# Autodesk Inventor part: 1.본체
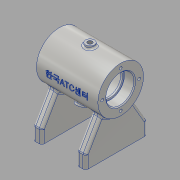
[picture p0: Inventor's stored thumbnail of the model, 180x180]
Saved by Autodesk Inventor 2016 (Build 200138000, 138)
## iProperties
Created: 2018-05
Part Number: 1.본체
Material: 알루미늄 6061
Document SubType Name: Modeling
Designer: 605-15
Density: 2.7 g/cm^3
Appearance: 알루미늄 - 평지
Mass: 317.681 g
Surface Area: 375.844 cm^2
Volume: 117.66 cm^3
Author: 605-15
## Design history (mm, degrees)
sketch "스케치1"
  geometry: L1 (-35, 0)-(35, 0); L2 (-35, 16)-(-35, 26); L3 (-35, 26)-(35, 26); L4 (35, 26)-(35, 16); L5 (35, 16)-(23, 16); L6 (23, 16)-(23, 14); L7 (23, 14)-(21, 14); L8 (21, 14)-(21, 21); L9 (21, 21)-(-21, 21); L10 (-21, 21)-(-21, 14); L11 (-21, 14)-(-23, 14); L12 (-23, 14)-(-23, 16); L13 (-23, 16)-(-35, 16); 1 further point
  constraints: 26 end point, 10 perpendicular, 3 point on line, 2 collinear, 2 vertical alignment, 1 horizontal, 1 midpoint, 1 vertical
  dimensions: "d0" = 70 distance of L1.start L1.end; "d1" = 35 distance of point (0, 0) L1.start; "d2" = 52 diameter of L3 L1; "d3" = 32 diameter of L5 L1; "d4" = 42 diameter of L9 L1; "d5" = 28 diameter of L7 L1; "d6" = 12 distance of L4.end L5.end; "d7" = 42 distance of L8.end L9.end
revolve "회전1" sketch "스케치1" stored, may be unused: angle "d8" = 90 deg
sketch "스케치2"
  geometry: L1 (-19.386, -17.325)-(-50, -35); L2 (-50, -35)-(-65, -35); L3 (-65, -35)-(-65, 35); L4 (-65, 35)-(-50, 35); L5 (-50, 35)-(-19.386, 17.325); A1 r 26 centre (0, 0) between (-19.386, -17.325) and (-19.386, 17.325) reference; 2 further points
  constraints: 10 end point, 2 perpendicular, 2 point on circle, 1 equal length, 1 horizontal, 1 horizontal alignment, 1 midpoint
  dimensions: "d9" = 30 deg angle of L4 L5; "d10" = 15 distance of L3.end L4.end; "d11" = 65 distance from line of point (0, 0) L3; "d12" = 70 distance between parallel lines of L2 L4; "d13" = 30 deg angle of L2 L1 (= d9)
extrude "돌출1" join sketch "스케치2" stored distance "d14" = 60; taper "d15" = 0 deg
sketch "스케치3"
  geometry: L1 (-19.386, 17.325)-(-50, 35) reference; L2 (-50, 35)-(-65, 35) reference; L3 (-65, 35)-(-65, -35) reference; L4 (-65, -35)-(-50, -35) reference; L5 (-50, -35)-(-19.386, -17.325) reference; A1 r 26 centre (0, 0) between (-19.386, 17.325) and (-19.386, -17.325) reference; 1 further point
extrude "돌출2" cut sketch "스케치3" stored distance "d16" = 40; taper "d17" = 0 deg
sketch "스케치4" dims "d18" = 42
  geometry: 3 further points
  constraints: 2 vertical alignment, 1 coincident, 2 other
hole "구멍1" sketch "스케치4" at (0, 21) diameter "d19" = 3.242; stored, may be unused: countersink angle "d23" = 90 deg, drill point angle "d25" = 118 deg; dims "d20" = 8, "d21" = 4, "d22" = 2, "d24" = 10
node "작업 평면1"
sketch "스케치5"
  geometry: C1 r 5 at (0, 0); 1 further point
  constraints: 1 centre point, 1 coincident
  dimensions: "d30" = 10 diameter of C1
extrude "돌출3" join sketch "스케치5" stored distance "d31" = 40; taper "d32" = 0 deg
sketch "스케치6"
  geometry: 1 further point
hole "구멍2" sketch "스케치6" at (0, 0) diameter "d33" = 5.188; stored, may be unused: countersink angle "d37" = 90 deg, drill point angle "d39" = 118 deg; dims "d34" = 16, "d35" = 4, "d36" = 2, "d38" = 16
sketch "스케치7"
  geometry: L1 (0, 0)-(-27.251, 9.919); L2 (0, 0)-(29, 0)
  constraints: 4 end point, 1 equal length, 1 horizontal
  dimensions: "d40" = 29 distance of L1.start L1.end; "d41" = 160 deg angle of L2 L1
node "작업 평면2"
sketch "스케치8"
  geometry: C1 r 6 at (0, 0); 1 further point
  constraints: 1 centre point, 1 coincident
  dimensions: "d42" = 12 diameter of C1
extrude "돌출4" join sketch "스케치8" stored distance "d43" = 40; taper "d44" = 0 deg
hole "구멍3" diameter "d47" = 5.188; stored, may be unused: countersink angle "d51" = 90 deg, drill point angle "d53" = 118 deg; dims "d45" = 10, "d46" = 10, "d48" = 16, "d49" = 4, "d50" = 2, "d52" = 16
sketch "스케치9"
  geometry: 5 further points
  constraints: 2 horizontal alignment, 2 vertical alignment
  dimensions: "d54" = 20 vertical distance of point (-30, 35) point (-5, 15); "d55" = 50 distance of point (-55, 15) point (-5, 15); "d56" = 25 horizontal distance of point (-30, 35) point (-5, 15); "d57" = 20 vertical distance of point (-5, 55) point (-30, 35)
hole "구멍4" sketch "스케치9" at (-5, 55), (-5, 15), (-55, 55), (-55, 15) diameter "d58" = 4.134; stored, may be unused: countersink angle "d62" = 90 deg, drill point angle "d64" = 118 deg; dims "d59" = 8, "d60" = 4, "d61" = 2, "d63" = 10
node "작업 평면3"
sketch "스케치10"
  geometry: L1 (-35, -26)-(-35, 26) reference; 2 further points
  constraints: 1 other
  dimensions: "d65" = 35 distance from line of L1 point (0, 0); "d66" = 26 vertical distance of L1.end point (0, 0)
feature "엠보싱1" sketch "스케치10" dims "d67" = 0.5, "d68" = 0
fillet "모깎기1" dims "d69" = 0.3
fillet "모깎기2" dims "d70" = 3
fillet "모깎기3" dims "d71" = 2
fillet "모깎기4" dims "d72" = 3
fillet "모깎기5" dims "d73" = 3
fillet "모깎기6" dims "d74" = 3
chamfer "모따기1" distance "d75" = 1; stored, may be unused: second distance "d76" = 2, angle "d77" = 45 deg
node "솔리드1"
pattern_circular "원형 패턴1" dims angle "d27" = 360 deg
mirror "대칭1"
node "투영된 루프1"
other parameters: "d29" = 29
